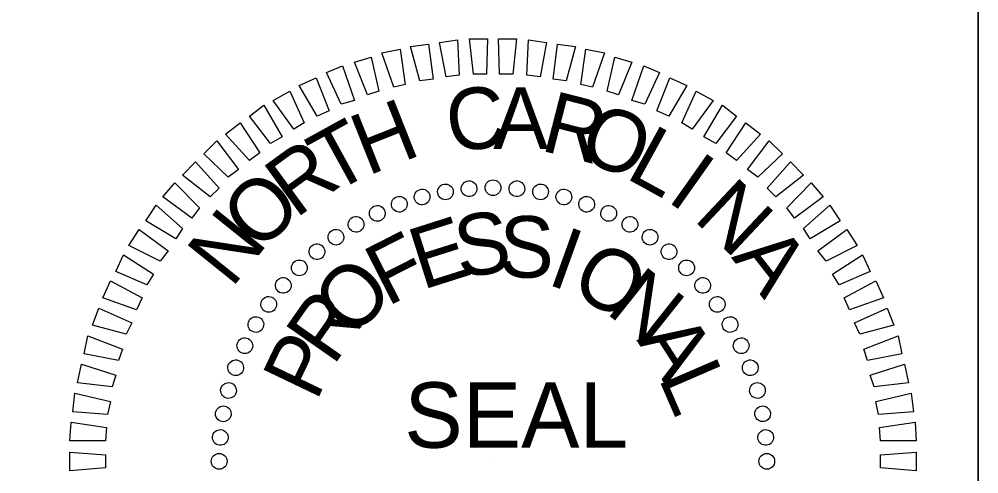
# Model space of a CAD drawing. Extents: x 2113883 to 2114903, y 714180 to 714840.
# Drawn here: x 2114763.5 to 2114822.8, y 714763.2 to 714791.4 of the extents above; entities that cross this region are included whole.
import ezdxf

# ---------------------------------------------------------------- set-up
doc = ezdxf.new("R2010")
doc.units = 0
for name, color, linetype in [('Default', 7, 'Continuous'), ('Sheet Border Standard 30in CELL', 7, 'Continuous'), ('Sheet Professional Seal CELL', 7, 'Continuous')]:
    doc.layers.add(name, color=color, linetype=linetype)

# ---------------------------------------------------------------- blocks, each defined once
blk = doc.blocks.new('POINT_DISPLAY')
at = {"layer": 'Default'}
blk.add_line((0, 0), (0, 0), dxfattribs=at)

msp = doc.modelspace()

# ---------------------------------------------------------------- linework, layer by layer
at = {"layer": 'Sheet Border Standard 30in CELL'}
for points in [[(2114762.734, 714802.756), (2114822.764, 714802.756), (2114822.764, 714735.256), (2114762.734, 714735.256)], [(2114822.764, 714802.756), (2114882.765, 714802.756), (2114882.765, 714735.256), (2114822.764, 714735.256)]]:
    msp.add_lwpolyline(points, close=True, dxfattribs=at)
at = {"layer": 'Sheet Professional Seal CELL'}
for points in [[(2114789.86, 714787.804), (2114789.456, 714789.931), (2114790.57, 714790.099), (2114790.671, 714787.905)], [(2114791.548, 714787.973), (2114791.313, 714790.167), (2114792.426, 714790.167), (2114792.359, 714787.973)], [(2114793.169, 714787.973), (2114793.102, 714790.167), (2114794.215, 714790.167), (2114793.979, 714787.973)], [(2114794.857, 714787.905), (2114794.958, 714790.099), (2114796.072, 714789.931), (2114795.667, 714787.804)], [(2114786.62, 714787.162), (2114785.877, 714789.289), (2114787.025, 714789.525), (2114787.328, 714787.331)], [(2114788.24, 714787.567), (2114787.666, 714789.694), (2114788.781, 714789.829), (2114789.051, 714787.668)], [(2114796.477, 714787.669), (2114796.747, 714789.83), (2114797.861, 714789.694), (2114797.287, 714787.568)], [(2114798.198, 714787.331), (2114798.503, 714789.525), (2114799.649, 714789.289), (2114798.908, 714787.162)], [(2114785, 714786.689), (2114784.189, 714788.714), (2114785.237, 714789.019), (2114785.708, 714786.926)], [(2114799.818, 714786.926), (2114800.291, 714789.019), (2114801.337, 714788.715), (2114800.528, 714786.689)], [(2114783.38, 714786.116), (2114782.468, 714788.074), (2114783.447, 714788.479), (2114784.189, 714786.352)], [(2114801.337, 714786.352), (2114802.08, 714788.479), (2114803.06, 714788.074), (2114802.148, 714786.116)], [(2114781.894, 714785.373), (2114780.78, 714787.263), (2114781.827, 714787.736), (2114782.637, 714785.711)], [(2114802.891, 714785.711), (2114803.7, 714787.736), (2114804.748, 714787.263), (2114803.634, 714785.373)], [(2114780.443, 714784.563), (2114779.161, 714786.351), (2114780.206, 714786.926), (2114781.084, 714784.968)], [(2114804.443, 714784.968), (2114805.322, 714786.926), (2114806.368, 714786.352), (2114805.085, 714784.563)], [(2114778.992, 714783.685), (2114777.708, 714785.373), (2114778.586, 714786.048), (2114779.733, 714784.091)], [(2114805.794, 714784.091), (2114806.942, 714786.049), (2114807.819, 714785.374), (2114806.536, 714783.686)], [(2114777.708, 714782.638), (2114776.223, 714784.26), (2114777.135, 714784.968), (2114778.35, 714783.111)], [(2114807.178, 714783.111), (2114808.393, 714784.968), (2114809.305, 714784.26), (2114807.819, 714782.638)], [(2114776.392, 714781.592), (2114774.873, 714783.043), (2114775.682, 714783.854), (2114777.033, 714782.065)], [(2114808.494, 714782.066), (2114809.844, 714783.854), (2114810.655, 714783.044), (2114809.136, 714781.593)], [(2114775.279, 714780.378), (2114773.556, 714781.728), (2114774.367, 714782.537), (2114775.818, 714780.917)], [(2114809.71, 714780.917), (2114811.161, 714782.537), (2114811.971, 714781.728), (2114810.25, 714780.378)], [(2114774.13, 714779.06), (2114772.341, 714780.378), (2114773.084, 714781.255), (2114774.603, 714779.702)], [(2114810.925, 714779.703), (2114812.444, 714781.255), (2114813.187, 714780.378), (2114811.398, 714779.061)], [(2114773.151, 714777.778), (2114771.294, 714778.892), (2114771.936, 714779.871), (2114773.556, 714778.419)], [(2114811.971, 714778.419), (2114813.592, 714779.872), (2114814.233, 714778.892), (2114812.376, 714777.778)], [(2114772.173, 714776.393), (2114770.248, 714777.373), (2114770.89, 714778.352), (2114772.679, 714777.035)], [(2114812.849, 714777.036), (2114814.638, 714778.352), (2114815.28, 714777.373), (2114813.356, 714776.394)], [(2114771.362, 714774.942), (2114769.438, 714775.753), (2114769.911, 714776.799), (2114771.767, 714775.584)], [(2114813.761, 714775.584), (2114815.618, 714776.799), (2114816.089, 714775.753), (2114814.165, 714774.942)], [(2114770.721, 714773.39), (2114768.628, 714774.132), (2114769.1, 714775.179), (2114771.059, 714774.133)], [(2114814.469, 714774.133), (2114816.427, 714775.179), (2114816.9, 714774.133), (2114814.807, 714773.39)], [(2114770.079, 714771.871), (2114767.986, 714772.445), (2114768.392, 714773.491), (2114770.417, 714772.579)], [(2114815.111, 714772.579), (2114817.137, 714773.491), (2114817.541, 714772.445), (2114815.449, 714771.871)], [(2114769.606, 714770.251), (2114767.48, 714770.655), (2114767.716, 714771.77), (2114769.843, 714770.959)], [(2114815.684, 714770.959), (2114817.812, 714771.77), (2114818.047, 714770.655), (2114815.92, 714770.251)], [(2114769.202, 714768.629), (2114767.075, 714768.866), (2114767.311, 714770.014), (2114769.438, 714769.339)], [(2114816.089, 714769.339), (2114818.216, 714770.014), (2114818.452, 714768.866), (2114816.326, 714768.629)], [(2114768.931, 714766.908), (2114766.772, 714767.077), (2114766.906, 714768.225), (2114769.1, 714767.719)], [(2114816.427, 714767.719), (2114818.621, 714768.225), (2114818.757, 714767.077), (2114816.596, 714766.909)], [(2114768.797, 714765.288), (2114766.603, 714765.288), (2114766.671, 714766.435), (2114768.865, 714766.098)], [(2114816.664, 714766.098), (2114818.858, 714766.435), (2114818.925, 714765.288), (2114816.731, 714765.288)], [(2114768.797, 714763.6), (2114766.603, 714763.432), (2114766.603, 714764.578), (2114768.797, 714764.41)], [(2114816.731, 714764.41), (2114818.925, 714764.579), (2114818.926, 714763.432), (2114816.731, 714763.601)]]:
    msp.add_lwpolyline(points, close=True, dxfattribs=at)
for centre, major_axis in [((2114789.82, 714780.686), (-0.084, 0.479)), ((2114791.284, 714780.879), (-0.042, 0.484)), ((2114792.76, 714780.944), (0, 0.486)), ((2114794.236, 714780.879), (0.042, 0.484)), ((2114795.7, 714780.686), (0.084, 0.479)), ((2114788.378, 714780.367), (-0.126, 0.47)), ((2114797.142, 714780.367), (0.126, 0.47)), ((2114786.969, 714779.922), (-0.166, 0.457)), ((2114798.551, 714779.922), (0.166, 0.457)), ((2114785.604, 714779.357), (-0.205, 0.441)), ((2114799.916, 714779.357), (0.205, 0.441)), ((2114784.294, 714778.675), (-0.243, 0.421)), ((2114801.226, 714778.675), (0.243, 0.421)), ((2114783.048, 714777.881), (-0.279, 0.398)), ((2114802.472, 714777.881), (0.279, 0.398)), ((2114781.876, 714776.982), (-0.312, 0.372)), ((2114803.644, 714776.982), (0.312, 0.372)), ((2114780.787, 714775.984), (-0.344, 0.344)), ((2114804.733, 714775.984), (0.344, 0.344)), ((2114779.789, 714774.895), (-0.372, 0.312)), ((2114805.731, 714774.895), (0.372, 0.312)), ((2114778.89, 714773.723), (-0.398, 0.279)), ((2114806.63, 714773.723), (0.398, 0.279)), ((2114778.096, 714772.477), (-0.421, 0.243)), ((2114807.424, 714772.478), (0.421, 0.243)), ((2114777.414, 714771.167), (-0.441, 0.205)), ((2114808.106, 714771.167), (0.441, 0.205)), ((2114776.849, 714769.802), (-0.457, 0.166)), ((2114808.671, 714769.803), (0.457, 0.166)), ((2114776.405, 714768.394), (-0.47, 0.126)), ((2114809.115, 714768.394), (0.47, 0.126)), ((2114776.085, 714766.951), (-0.479, 0.084)), ((2114809.435, 714766.952), (0.479, 0.084)), ((2114775.892, 714765.487), (-0.484, 0.042)), ((2114809.628, 714765.487), (0.484, 0.042)), ((2114775.828, 714764.011), (-0.486, 0)), ((2114809.692, 714764.011), (0.486, 0))]:
    msp.add_ellipse(centre, major_axis=major_axis, ratio=0.999708, dxfattribs=at)

# ---------------------------------------------------------------- block references
at = {"layer": 'Sheet Professional Seal CELL', "xscale": 41.411959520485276, "yscale": 41.41195952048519, "rotation": 0.00042986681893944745}
for p in [(2114789.827, 714780.681), (2114791.278, 714780.884), (2114792.764, 714780.95), (2114794.249, 714780.884), (2114795.701, 714780.681), (2114788.376, 714780.378), (2114797.152, 714780.378), (2114786.958, 714779.938), (2114798.57, 714779.938), (2114785.608, 714779.365), (2114799.921, 714779.365), (2114784.291, 714778.69), (2114801.237, 714778.69), (2114783.043, 714777.879), (2114802.486, 714777.879), (2114781.861, 714777.002), (2114803.667, 714777.002), (2114780.781, 714775.989), (2114804.748, 714775.989), (2114779.768, 714774.909), (2114805.76, 714774.909), (2114778.889, 714773.727), (2114806.637, 714773.727), (2114778.08, 714772.478), (2114807.448, 714772.478), (2114777.405, 714771.161), (2114808.123, 714771.161), (2114776.831, 714769.811), (2114808.697, 714769.811), (2114776.392, 714768.394), (2114809.136, 714768.394), (2114776.088, 714766.941), (2114775.886, 714765.49), (2114809.643, 714765.49), (2114775.818, 714764.006), (2114792.764, 714764.006), (2114809.71, 714764.006)]:
    msp.add_blockref('POINT_DISPLAY', p, dxfattribs=at)

# ---------------------------------------------------------------- texts
at = {"layer": 'Sheet Professional Seal CELL'}
for s, height, rotation, p in [('C', 3.806, 7.2203, (2114790.104, 714783.112)), ('A', 3.806, 0.02075, (2114792.773, 714783.348)), ('R', 3.806, 345.62153, (2114795.605, 714783.278)), ('H', 3.806, 21.61991, (2114785.001, 714781.66)), ('O', 3.806, 338.42159, (2114797.87, 714782.803)), ('T', 3.806, 28.8202, (2114782.808, 714780.513)), ('L', 3.806, 331.2213, (2114800.872, 714781.589)), ('R', 3.806, 36.02094, (2114780.549, 714778.996)), ('I', 3.806, 324.781, (2114803.424, 714780.18)), ('O', 3.806, 43.22217, (2114778.256, 714776.873)), ('N', 3.806, 316.81934, (2114805.088, 714778.99)), ('N', 3.806, 51.1609, (2114776.594, 714774.67)), ('S', 3.807, 8.25604, (2114790.671, 714775.347)), ('E', 3.807, 17.6115, (2114788.373, 714774.603)), ('S', 3.807, 358.90083, (2114793.102, 714775.415)), ('F', 3.807, 26.96746, (2114786.212, 714773.557)), ('I', 3.807, 340.19003, (2114796.009, 714775.008)), ('A', 3.806, 308.06255, (2114807.464, 714776.634)), ('O', 3.807, 330.83391, (2114797.397, 714774.532)), ('O', 3.807, 45.68167, (2114784.027, 714771.54)), ('N', 3.807, 321.47704, (2114799.653, 714773.252)), ('R', 3.807, 55.04008, (2114782.877, 714769.85)), ('A', 3.807, 302.7607, (2114801.613, 714771.526)), ('P', 3.807, 64.39932, (2114781.829, 714767.656)), ('L', 3.807, 293.40128, (2114802.962, 714769.196)), ('SEAL', 4.0496, 0.00043, (2114787.277, 714764.85))]:
    msp.add_text(s, height=height, rotation=rotation, dxfattribs=at).set_placement(p)

doc.saveas('drawing.dxf')
